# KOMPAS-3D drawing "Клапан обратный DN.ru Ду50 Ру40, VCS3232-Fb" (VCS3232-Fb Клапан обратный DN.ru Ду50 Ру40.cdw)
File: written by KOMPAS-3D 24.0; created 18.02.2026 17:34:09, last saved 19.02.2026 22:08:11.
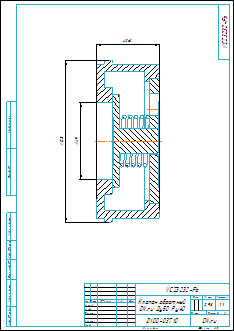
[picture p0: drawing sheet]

Document properties: v313: 1; D: 58; d: 20; a: 1; L: 28; Артикул: D100-03710; Автор: R2D2; Форматы листов документа: A3; Полное имя файла: VCS3232-Fb Клапан обратный DN.ru Ду50 Ру40.m3d; Масса: 0.981; Наименование: Клапан обратный DN.ru Ду50 Ру40; Количество листов документа: 1; Примечание: D100-03710

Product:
- Body: Тело 1  | qty 1
    Масса: 0.806125
- Body: Тело 2  | qty 1
    Масса: 0.317881
- Part/product: Клапан обратный DN.ru Ду50 Ру40  | designation VCS3232-Fb
    Масса: 0.981
    Примечание: D100-03710
    additional columns: 1; D100-03710

Views: Вид 1, Местный разрез 1, Справа
Referenced files in E:\Работа\Зайцев\VCS3232-Fb Клапан обратный DN.ru Ду15-100\DN32\: VCS3232-Fb Клапан обратный DN.ru Ду32 Ру40.m3d
Referenced files in E:\Работа\Зайцев\VCS3232-Fb Клапан обратный DN.ru Ду15-100\DN25\: VCS3232-Fb Клапан обратный DN.ru Ду25 Ру40.m3d
Referenced files in E:\Работа\Зайцев\VCS3232-Fb Клапан обратный DN.ru Ду15-100\DN50\: VCS3232-Fb Клапан обратный DN.ru Ду50 Ру40.m3d
Referenced files in E:\Работа\Зайцев\Для компаса\: чертеж DN.ru.cdt
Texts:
  VCS3232-Fb
  чертеж DN.ru.cdt
  Клапан обратный
  DN.ru Ду50 Ру40
  prop
  Клапан обратный DN.ru Ду50 Ру40
  VCS3232-Fb Клапан обратный DN.ru Ду50 Ру40
Dimensions and other numbers on the sheet: 0; 3; 2; 4; 49; 103; 40±2; 6; 2:1; 1; 0,98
